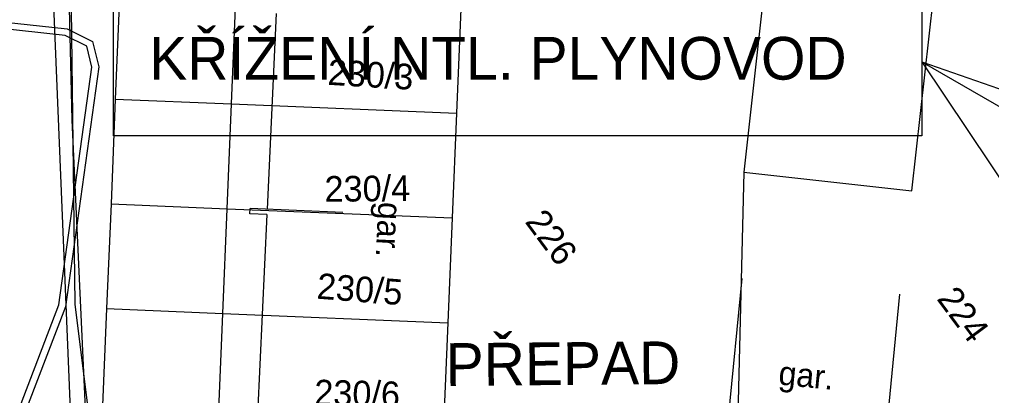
# Model space of a CAD drawing. Extents: x -601580 to 4, y -1204314 to 4.
# Drawn here: x -595963.73 to -595935.25, y -1202911.44 to -1202900.44 of the extents above; entities that cross this region are included whole.
import ezdxf

# ---------------------------------------------------------------- set-up
doc = ezdxf.new("R2010")
doc.units = 0
for name, color, linetype in [('00-EON NN', 7, 'Continuous'), ('00-KN-HRANICE PARCEL', 7, 'Continuous'), ('00-KN-PARC. CISLA', 7, 'Continuous'), ('00-KN-VNITRNI KRESBA', 7, 'Continuous'), ('00-POLOHOPIS', 7, 'Continuous'), ('00-SITE KOM. KABEL', 7, 'Continuous'), ('11-REKONSTRUKCE KANALIZACE', 7, 'Continuous'), ('11-REKONSTRUKCE KANALIZACE POPIS', 7, 'Continuous')]:
    doc.layers.add(name, color=color, linetype=linetype)

msp = doc.modelspace()

# ---------------------------------------------------------------- linework, layer by layer
at = {"layer": '00-EON NN'}
for points in [[(-595962.795, -1202889.704), (-595962.216, -1202900.128), (-595962.106, -1202908.764), (-595960.976, -1202917.821), (-595961.476, -1202918.321)], [(-595965.666, -1202918.514), (-595964.53, -1202918.224), (-595964.419, -1202915.236), (-595964.219, -1202913.069), (-595962.576, -1202908.788), (-595961.611, -1202901.83), (-595961.755, -1202901.221), (-595962.388, -1202900.907), (-595966.586, -1202900.449), (-595968.107, -1202900.476), (-595968.775, -1202900.47), (-595972.017, -1202900.119), (-595978.843, -1202897.716), (-595981.803, -1202896.974), (-595984.13, -1202896.687), (-595987.99, -1202896.577), (-595989.056, -1202895.961), (-595989.578, -1202895.42), (-595989.661, -1202894.856), (-595989.391, -1202893.05), (-595988.707, -1202891.551), (-595988.526, -1202889.968)], [(-595987.594, -1202889.968), (-595987.751, -1202890.467), (-595989.049, -1202893.163), (-595989.122, -1202894.942), (-595988.775, -1202895.486), (-595987.83, -1202895.882), (-595983.835, -1202896.084), (-595981.486, -1202896.421), (-595978.772, -1202897.343), (-595971.89, -1202899.588), (-595968.767, -1202900.269), (-595966.578, -1202900.249), (-595962.33, -1202900.713), (-595961.583, -1202901.083), (-595961.406, -1202901.82), (-595962.382, -1202908.839), (-595964.023, -1202913.115), (-595964.22, -1202915.25), (-595964.334, -1202918.376), (-595965.621, -1202918.71)]]:
    msp.add_lwpolyline(points, dxfattribs=at)
at = {"layer": '00-KN-HRANICE PARCEL'}
for p, q in [((-595960.796, -1202899.708), (-595960.919, -1202902.763)), ((-595950.8, -1202900.122), (-595950.923, -1202903.177)), ((-595960.919, -1202902.763), (-595961.044, -1202905.833)), ((-595950.923, -1202903.177), (-595951.054, -1202906.238)), ((-595961.044, -1202905.833), (-595961.175, -1202908.894)), ((-595951.054, -1202906.238), (-595951.179, -1202909.308)), ((-595961.175, -1202908.894), (-595961.301, -1202911.964)), ((-595951.179, -1202909.308), (-595951.31, -1202912.369))]:
    msp.add_line(p, q, dxfattribs=at)
for points in [[(-595941.201, -1202893.221), (-595942.507, -1202904.901), (-595942.71, -1202913.184), (-595942.841, -1202918.461)], [(-595960.919, -1202902.763), (-595957.516, -1202902.902), (-595950.923, -1202903.177)], [(-595961.044, -1202905.833), (-595957.641, -1202905.972), (-595951.054, -1202906.238)], [(-595961.175, -1202908.894), (-595957.772, -1202909.033), (-595951.179, -1202909.308)]]:
    msp.add_lwpolyline(points, dxfattribs=at)
at = {"layer": '00-KN-VNITRNI KRESBA'}
for p, q in [((-595937.578, -1202905.451), (-595936.243, -1202893.526)), ((-595957.516, -1202902.902), (-595957.392, -1202899.847)), ((-595957.641, -1202905.972), (-595957.516, -1202902.902)), ((-595942.507, -1202904.901), (-595937.578, -1202905.451)), ((-595957.772, -1202909.033), (-595957.641, -1202905.972)), ((-595957.897, -1202912.102), (-595957.772, -1202909.033))]:
    msp.add_line(p, q, dxfattribs=at)
at = {"layer": '00-POLOHOPIS'}
for p, q in [((-595961.975, -1202918.011), (-595962.981, -1202893.72)), ((-595956.205, -1202900.265), (-595956.472, -1202905.984)), ((-595956.98, -1202906.12), (-595956.971, -1202905.961)), ((-595956.481, -1202906.143), (-595956.98, -1202906.12)), ((-595954.254, -1202906.086), (-595956.971, -1202905.961)), ((-595956.481, -1202906.143), (-595956.753, -1202911.989)), ((-595942.566, -1202908.017), (-595943.05, -1202912.994)), ((-595937.942, -1202908.467), (-595938.426, -1202913.444))]:
    msp.add_line(p, q, dxfattribs=at)
at = {"layer": '00-SITE KOM. KABEL'}
msp.add_lwpolyline([(-595962.653, -1202889.719), (-595962.437, -1202893.118), (-595962.19, -1202903.383), (-595961.704, -1202913.92), (-595961.215, -1202919.696), (-595960.751, -1202920.958), (-595958.852, -1202921.84), (-595941.614, -1202919.207), (-595919.364, -1202915.93), (-595914.802, -1202915.533), (-595909.726, -1202915.29), (-595904.77, -1202915.172), (-595892.698, -1202914.792), (-595882.435, -1202914.609), (-595868.371, -1202914.195), (-595862.284, -1202914.073), (-595852.26, -1202913.769), (-595831.47, -1202912.098)], dxfattribs=at)
at = {"layer": '11-REKONSTRUKCE KANALIZACE POPIS'}
for q in [(-595924.837, -1202920.263), (-595909.864, -1202917.494), (-595893.541, -1202916.916)]:
    msp.add_line((-595937.294, -1202901.673), q, dxfattribs=at)
msp.add_lwpolyline([(-595960.971, -1202899.506), (-595937.294, -1202899.506), (-595937.294, -1202903.841), (-595960.971, -1202903.841)], close=True, dxfattribs=at)

# ---------------------------------------------------------------- texts
at = {"layer": '00-KN-PARC. CISLA'}
for s, rotation, p in [('230/3', 356.5853, (-595954.713, -1202902.346)), ('230/4', 0.5853, (-595954.786, -1202905.77)), ('226', 306.5853, (-595948.937, -1202906.356)), ('230/5', 355.5853, (-595955.035, -1202908.601)), ('224', 306.5853, (-595936.872, -1202908.611)), ('230/6', 358.5853, (-595955.097, -1202911.72))]:
    msp.add_text(s, height=0.75, rotation=rotation, dxfattribs=at).set_placement(p)
at = {"layer": '00-POLOHOPIS'}
for rotation, p in [(267.3156, (-595953.213, -1202905.765)), (354.4442, (-595941.508, -1202911.115))]:
    msp.add_text('gar.', height=0.7, rotation=rotation, dxfattribs=at).set_placement(p)
at = {"layer": '11-REKONSTRUKCE KANALIZACE'}
msp.add_text('PŘEPAD', height=1.25, rotation=0.487, dxfattribs=at).set_placement((-595951.235, -1202911.157))
at = {"layer": '11-REKONSTRUKCE KANALIZACE POPIS'}
msp.add_text('KŘÍŽENÍ NTL. PLYNOVOD', height=1.25, dxfattribs=at).set_placement((-595959.927, -1202902.197))

doc.saveas('drawing.dxf')
